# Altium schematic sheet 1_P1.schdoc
size 307 x 218 mm; Symbol: Drawing-Symbol_A4; Device: Drawing-Symbol_A4; Company: 嘉立创EDA; Version: V1.0; Page Size: A4; @Project Name: HDMI2CSI; @Page Count: 1; @Update Date: 2025-08-11; @Create Date: 2025-08-11; @Schematic Name: FPC; @Page No: 1; @Page Name: P1; @Create Time: 11:44:26; @Update Time: 13:22:26; Width: 1170; Height: 825; Region Start: 1; X Region Count: 6; Y Region Count: 4; Blade Width: 10; Title Block Position: 3; @Board Name: FPC
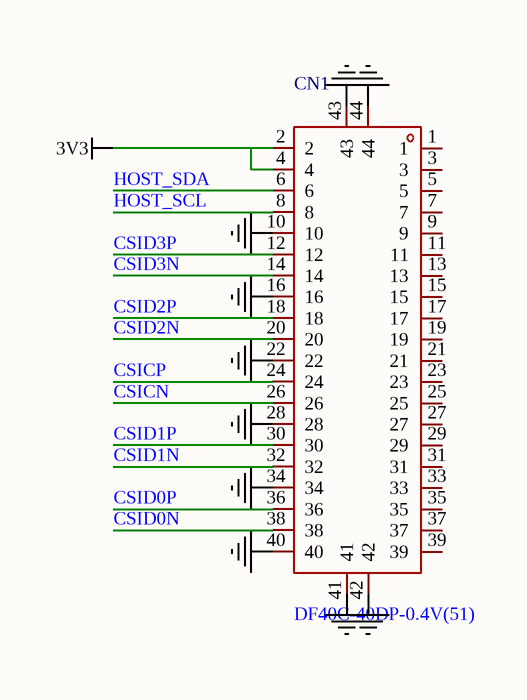
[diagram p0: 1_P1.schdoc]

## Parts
CN1  DF40C-40DP-0.4V(51)  [CONN-SMD_DF40C-40DP-0.4V]

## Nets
3V3: CN1.2 CN1.4
GND: CN1.10 CN1.16 CN1.22 CN1.28 CN1.34 CN1.40 CN1.41 CN1.42 CN1.43 CN1.44
CSICN: CN1.26
CSICP: CN1.24
CSID0N: CN1.38
CSID0P: CN1.36
CSID1N: CN1.32
CSID1P: CN1.30
CSID2N: CN1.20
CSID2P: CN1.18
CSID3N: CN1.14
CSID3P: CN1.12
HOST_SCL: CN1.8
HOST_SDA: CN1.6

Not connected (* = marked no-connect by the designer): CN1 1 3 5 7 9 11 13 15 17 19 21 23 25 27 29 31 33 35 37 39

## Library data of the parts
CN1 = DF40C-40DP-0.4V(51): Manufacturer: HRS(广濑); Add into BOM: yes; Pitch: 0.4mm; Current Rating (Max): 300mA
